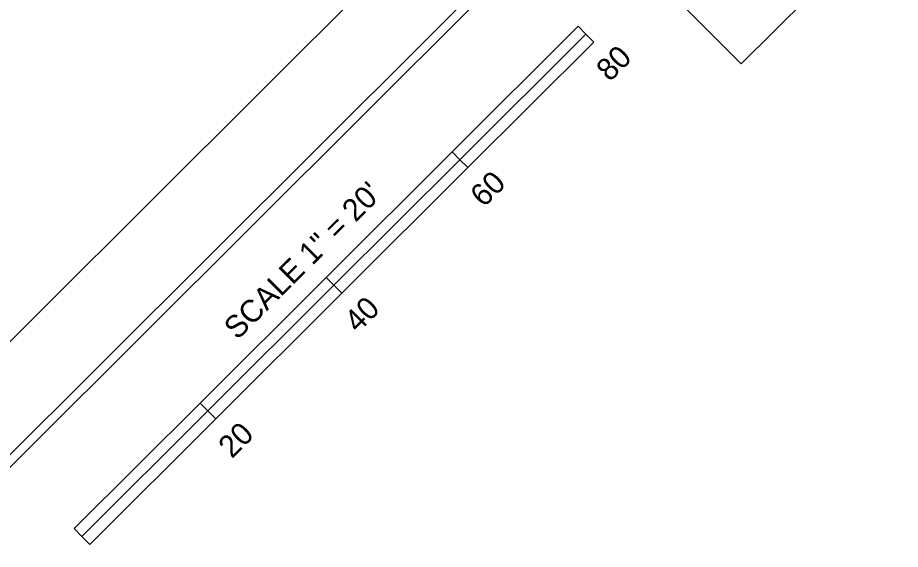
# Model space of a CAD drawing. Extents: x 1439200 to 1641361, y 392889 to 606444.
# Drawn here: x 1640876.6 to 1640975.9, y 393478 to 393537.8 of the extents above; entities that cross this region are included whole.
import ezdxf

# ---------------------------------------------------------------- set-up
doc = ezdxf.new("R2010")
doc.units = 0
for name, color, linetype in [('Old_Level_20', 7, 'Continuous'), ('Sheet Plot Border Inside CELL', 7, 'Continuous'), ('Sheet Plot Border Outside CELL', 7, 'Continuous'), ('Sheet Sticker Exception Certification CELL', 7, 'Continuous'), ('UC Plan Sheet 34 CELL', 7, 'Continuous')]:
    doc.layers.add(name, color=color, linetype=linetype)

msp = doc.modelspace()

# ---------------------------------------------------------------- linework, layer by layer
at = {"layer": 'Old_Level_20'}
for points in [[(1640926.343, 393521.786), (1640940.503, 393535.91), (1640939.62, 393536.795), (1640925.46, 393522.671), (1640926.343, 393521.786)], [(1640913.066, 393506.777), (1640927.226, 393520.901), (1640926.343, 393521.786), (1640912.183, 393507.662), (1640913.066, 393506.777)], [(1640898.023, 393493.538), (1640912.183, 393507.662), (1640911.3, 393508.547), (1640897.14, 393494.423), (1640898.023, 393493.538)], [(1640884.746, 393478.528), (1640898.906, 393492.653), (1640898.023, 393493.538), (1640883.863, 393479.413), (1640884.746, 393478.528)]]:
    msp.add_lwpolyline(points, dxfattribs=at)
for points in [[(1640926.343, 393521.786), (1640940.503, 393535.91), (1640941.385, 393535.025), (1640927.226, 393520.901)], [(1640911.3, 393508.547), (1640925.46, 393522.671), (1640926.343, 393521.786), (1640912.183, 393507.662)], [(1640898.023, 393493.538), (1640912.183, 393507.662), (1640913.066, 393506.777), (1640898.906, 393492.653)], [(1640882.98, 393480.298), (1640897.14, 393494.423), (1640898.023, 393493.538), (1640883.863, 393479.413)]]:
    msp.add_lwpolyline(points, close=True, dxfattribs=at)
at = {"layer": 'Sheet Plot Border Inside CELL'}
msp.add_lwpolyline([(1641055.702, 393668.151), (1640583.752, 393197.387), (1640881.803, 392898.584), (1641353.753, 393369.348)], close=True, dxfattribs=at)
at = {"layer": 'Sheet Plot Border Outside CELL'}
msp.add_lwpolyline([(1641050.634, 393675.78), (1640573.728, 393200.072), (1640884.463, 392888.554), (1641361.369, 393364.261)], close=True, dxfattribs=at)
at = {"layer": 'Sheet Sticker Exception Certification CELL'}
for p, q in [((1641014.618, 393589.07), (1640957.967, 393532.562)), ((1640957.967, 393532.562), (1640951.329, 393539.217))]:
    msp.add_line(p, q, dxfattribs=at)
at = {"layer": 'UC Plan Sheet 34 CELL'}
msp.add_lwpolyline([(1641052.882, 393663.897), (1640628.084, 393240.167), (1640924.695, 392942.809), (1641349.493, 393366.539)], close=True, dxfattribs=at)

# ---------------------------------------------------------------- texts
at = {"layer": 'Old_Level_20'}
for s, height, p in [('80', 2.5, (1640943.189, 393530.468)), ('60', 2.5, (1640929.029, 393516.344)), ('SCALE 1" = 20\'', 2.49999, (1640901.342, 393501.441)), ('40', 2.5, (1640914.869, 393502.22)), ('20', 2.5, (1640900.709, 393488.095))]:
    msp.add_text(s, height=height, rotation=44.92791, dxfattribs=at).set_placement(p)

doc.saveas('drawing.dxf')
